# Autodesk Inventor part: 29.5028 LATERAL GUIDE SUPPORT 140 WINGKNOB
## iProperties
Created: 2007-07
Part Number: 29.5028 LATERAL GUIDE SUPPORT 140 WINGKNOB
Material: ABS Plastic
Document SubType Name: Modeling
Designer: Andy Moles
Density: 1.06 g/cm^3
Author: Andy Moles
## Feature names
1. Base1
2. Chamfer1
